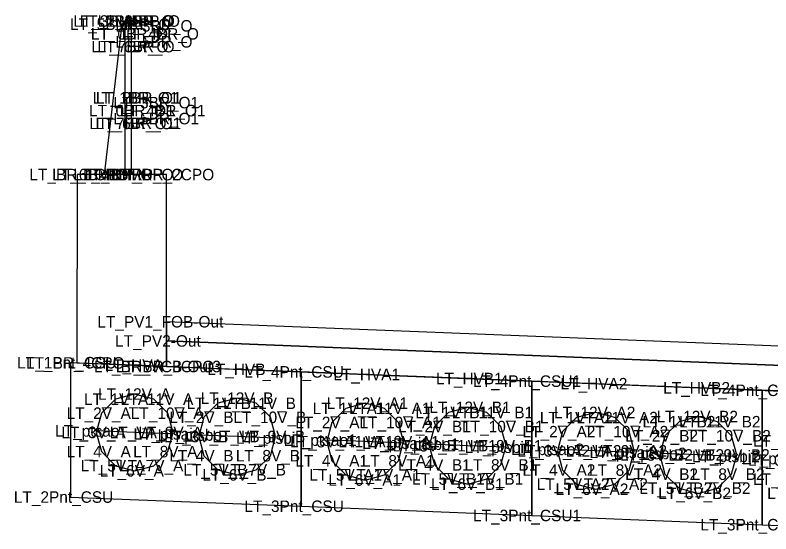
# Model space of a CAD drawing. Extents: x -26 to 1163, y -10 to 9537.
# Drawn here: x 59.53 to 69.36, y 6515.57 to 6522.32 of the extents above; entities that cross this region are included whole.
import ezdxf

# ---------------------------------------------------------------- set-up
doc = ezdxf.new("R2010")
doc.units = 0
for name, color, linetype in [('Prop CMT Bridge Metal Rail', 7, 'Continuous'), ('Prop CMT Bridge Metal Rail Post', 7, 'Continuous'), ('Prop CMT Concrete Structures', 7, 'Continuous'), ('Prop CMT Corridor Surface Symbology Blue', 7, 'Continuous'), ('Prop CMT Pvmt Course 1', 7, 'Continuous'), ('Prop CMT Pvmt Course 2', 7, 'Continuous'), ('Scratch_Level_0', 7, 'Continuous')]:
    doc.layers.add(name, color=color, linetype=linetype)

msp = doc.modelspace()

# ---------------------------------------------------------------- linework, layer by layer
at = {"layer": 'Prop CMT Bridge Metal Rail'}
for points in [[(61.0407, 6522.2467), (61.124, 6522.2467), (61.3532, 6522.1842), (61.4365, 6522.08)], [(61.0407, 6522.08), (61.0407, 6522.2467)], [(61.4365, 6522.08), (61.3532, 6521.9759), (61.124, 6521.9134), (61.0407, 6521.9134)], [(61.0407, 6521.9134), (61.0407, 6522.08)], [(61.0407, 6521.2467), (61.124, 6521.2467), (61.3532, 6521.1842), (61.4365, 6521.08)], [(61.0407, 6521.08), (61.0407, 6521.2467)], [(61.4365, 6521.08), (61.3532, 6520.9759), (61.124, 6520.9134), (61.0407, 6520.9134)], [(61.0407, 6520.9134), (61.0407, 6521.08)]]:
    msp.add_lwpolyline(points, dxfattribs=at)
at = {"layer": 'Prop CMT Bridge Metal Rail Post'}
for points in [[(60.9574, 6522.2467), (60.9157, 6522.205), (60.6865, 6520.2467)], [(61.0407, 6522.2467), (60.9574, 6522.2467)], [(60.9574, 6522.2467), (60.9574, 6520.2467)], [(61.0407, 6520.2467), (61.0407, 6522.2467)]]:
    msp.add_lwpolyline(points, dxfattribs=at)
at = {"layer": 'Prop CMT Concrete Structures'}
for points in [[(61.5, 6517.7467), (61.499, 6520.2467), (60.3343, 6520.2467), (60.3333, 6517.7934)], [(63.25, 6517.6767), (62.4167, 6517.71), (61.0833, 6517.7634), (60.25, 6517.7967)], [(60.25, 6517.7967), (60.25, 6516.0467)], [(60.3333, 6517.7934), (61.5, 6517.7467)], [(66.25, 6517.5567), (65.4167, 6517.59), (64.0833, 6517.6434), (63.25, 6517.6767)], [(63.25, 6517.6767), (63.25, 6515.9267)], [(63.25, 6515.9267), (63.25, 6517.6767)], [(69.25, 6517.4367), (68.4167, 6517.47), (67.0833, 6517.5234), (66.25, 6517.5567)], [(66.25, 6517.5567), (66.25, 6515.8067)], [(66.25, 6515.8067), (66.25, 6517.5567)], [(61.0833, 6517.3884), (60.8333, 6517.3214), (60.6503, 6517.1384), (60.5833, 6516.8884)], [(61.5833, 6516.8884), (61.5163, 6517.1384), (61.3333, 6517.3214), (61.0833, 6517.3884)], [(72.25, 6517.3167), (71.4167, 6517.35), (70.0833, 6517.4034), (69.25, 6517.4367)], [(69.25, 6517.4367), (69.25, 6515.6867)], [(69.25, 6515.6867), (69.25, 6517.4367)], [(62.4167, 6517.335), (62.1667, 6517.268), (61.9837, 6517.085), (61.9167, 6516.835)], [(62.9167, 6516.835), (62.8497, 6517.085), (62.6667, 6517.268), (62.4167, 6517.335)], [(64.0833, 6517.2684), (63.8333, 6517.2014), (63.6503, 6517.0184), (63.5833, 6516.7684)], [(64.5833, 6516.7684), (64.5163, 6517.0184), (64.3333, 6517.2014), (64.0833, 6517.2684)], [(65.4167, 6517.215), (65.1667, 6517.148), (64.9837, 6516.965), (64.9167, 6516.715)], [(65.9167, 6516.715), (65.8497, 6516.965), (65.6667, 6517.148), (65.4167, 6517.215)], [(67.0833, 6517.1484), (66.8333, 6517.0814), (66.6503, 6516.8984), (66.5833, 6516.6484)], [(67.5833, 6516.6484), (67.5163, 6516.8984), (67.3333, 6517.0814), (67.0833, 6517.1484)], [(68.4167, 6517.095), (68.1667, 6517.028), (67.9837, 6516.845), (67.9167, 6516.595)], [(68.9167, 6516.595), (68.8497, 6516.845), (68.6667, 6517.028), (68.4167, 6517.095)], [(60.5833, 6516.8884), (60.6503, 6516.6384), (60.8333, 6516.4554), (61.0833, 6516.3884), (61.3333, 6516.4554), (61.5163, 6516.6384), (61.5833, 6516.8884)], [(61.9167, 6516.835), (61.9837, 6516.585), (62.1667, 6516.402), (62.4167, 6516.335), (62.6667, 6516.402), (62.8497, 6516.585), (62.9167, 6516.835)], [(63.5833, 6516.7684), (63.6503, 6516.5184), (63.8333, 6516.3354), (64.0833, 6516.2684), (64.3333, 6516.3354), (64.5163, 6516.5184), (64.5833, 6516.7684)], [(64.9167, 6516.715), (64.9837, 6516.465), (65.1667, 6516.282), (65.4167, 6516.215), (65.6667, 6516.282), (65.8497, 6516.465), (65.9167, 6516.715)], [(66.5833, 6516.6484), (66.6503, 6516.3984), (66.8333, 6516.2154), (67.0833, 6516.1484), (67.3333, 6516.2154), (67.5163, 6516.3984), (67.5833, 6516.6484)], [(67.9167, 6516.595), (67.9837, 6516.345), (68.1667, 6516.162), (68.4167, 6516.095), (68.6667, 6516.162), (68.8497, 6516.345), (68.9167, 6516.595)], [(60.25, 6516.0467), (63.25, 6515.9267)], [(63.25, 6515.9267), (66.25, 6515.8067)], [(66.25, 6515.8067), (69.25, 6515.6867)], [(69.25, 6515.6867), (72.25, 6515.5667)]]:
    msp.add_lwpolyline(points, dxfattribs=at)
at = {"layer": 'Prop CMT Corridor Surface Symbology Blue'}
for points in [[(61.5733, 6516.8688), (61.0833, 6516.8884), (60.5933, 6516.908)], [(62.9067, 6516.8154), (62.4167, 6516.835), (61.9267, 6516.8546)], [(64.5733, 6516.7488), (64.0833, 6516.7684), (63.5933, 6516.788)], [(65.9067, 6516.6954), (65.4167, 6516.715), (64.9267, 6516.7346)], [(67.5733, 6516.6288), (67.0833, 6516.6484), (66.5933, 6516.668)], [(68.9067, 6516.5754), (68.4167, 6516.595), (67.9267, 6516.6146)]]:
    msp.add_lwpolyline(points, dxfattribs=at)
at = {"layer": 'Prop CMT Pvmt Course 1'}
for points in [[(80, 6517.59), (71, 6517.95), (61.4998, 6518.33)], [(61.4998, 6518.33), (61.4999, 6518.08)], [(61.4999, 6518.08), (80, 6517.34)]]:
    msp.add_lwpolyline(points, dxfattribs=at)
at = {"layer": 'Prop CMT Pvmt Course 2'}
for points in [[(80, 6517.34), (61.4999, 6518.08)], [(61.4999, 6518.08), (61.5, 6517.7467), (80, 6517.0067)]]:
    msp.add_lwpolyline(points, dxfattribs=at)

# ---------------------------------------------------------------- texts
at = {"layer": 'Scratch_Level_0'}
for s, p in [('LT_3BMRP_O', (60.2853, 6522.1717)), ('LT_2BMRP_O', (60.3687, 6522.1717)), ('LT_2BR_O', (60.6032, 6522.1717)), ('LT_5BMRP_O', (60.2437, 6522.13)), ('LT_3BR_O', (60.8323, 6522.1092)), ('LT_0BR_O', (60.5139, 6522.005)), ('LT_4BR_O', (60.9157, 6522.005)), ('LT_5BR_O', (60.8323, 6521.9009)), ('LT_7BR_O', (60.5198, 6521.8384)), ('LT_6BR_O', (60.5996, 6521.8384)), ('LT_1BR_O1', (60.5376, 6521.1717)), ('LT_2BR_O1', (60.5784, 6521.1717)), ('LT_3BR_O1', (60.8075, 6521.1092)), ('LT_0BR_O1', (60.4891, 6521.005)), ('LT_4BR_O1', (60.8909, 6521.005)), ('LT_5BR_O1', (60.8075, 6520.9009)), ('LT_7BR_O1', (60.495, 6520.8384)), ('LT_6BR_O1', (60.5748, 6520.8384)), ('LT_BR_1CPO', (59.7143, 6520.1717)), ('LT_6BMRP_O', (60.0109, 6520.1717)), ('LT_4BMRP_O', (60.2853, 6520.1717)), ('LT_1BMRP_O', (60.4112, 6520.1717)), ('LT_BR_2CPO', (60.8364, 6520.1717)), ('LT_PV1_FOB-Out', (60.5986, 6518.255)), ('LT_PV2-Out', (60.829, 6518.005)), ('LT_1Pnt_CSU', (59.5543, 6517.7217)), ('LT_BR_4CPO', (59.6707, 6517.7184)), ('LT_BR_VCB-Out3', (60.5552, 6517.6717)), ('LT_HVA', (60.6924, 6517.6884)), ('LT_BR_3CPO', (60.8374, 6517.6717)), ('LT_HVB', (62.0281, 6517.635)), ('LT_4Pnt_CSU', (62.5118, 6517.6017)), ('LT_HVA1', (63.6676, 6517.5684)), ('LT_HVB1', (65.0033, 6517.515)), ('LT_4Pnt_CSU1', (65.487, 6517.4817)), ('LT_HVA2', (66.6251, 6517.4484)), ('LT_HVB2', (67.9608, 6517.395)), ('LT_4Pnt_CSU2', (68.4445, 6517.3617)), ('LT_1V_A', (60.4235, 6517.2464)), ('LT_12V_A', (60.6062, 6517.3134)), ('LT_11V_A', (60.8987, 6517.2464)), ('LT_12V_B', (61.9419, 6517.26)), ('LT_1V_B', (61.7592, 6517.193)), ('LT_11V_B', (62.2344, 6517.193)), ('LT_12V_A1', (63.5814, 6517.1934)), ('LT_12V_B1', (64.9171, 6517.14)), ('LT_2V_A', (60.198, 6517.0634)), ('LT_10V_A', (61.0333, 6517.0634)), ('LT_1V_A1', (63.3987, 6517.1264)), ('LT_11V_A1', (63.8739, 6517.1264)), ('LT_1V_B1', (64.7344, 6517.073)), ('LT_11V_B1', (65.2096, 6517.073)), ('LT_12V_A2', (66.5388, 6517.0734)), ('LT_2V_B', (61.5337, 6517.01)), ('LT_10V_B', (62.369, 6517.01)), ('LT_2V_A1', (63.1732, 6516.9434)), ('LT_10V_A1', (64.0085, 6516.9434)), ('LT_1V_A2', (66.3562, 6517.0064)), ('LT_11V_A2', (66.8314, 6517.0064)), ('LT_1V_B2', (67.6919, 6516.953)), ('LT_12V_B2', (67.8745, 6517.02)), ('LT_11V_B2', (68.1671, 6516.953)), ('LT_2V_B1', (64.5089, 6516.89)), ('LT_10V_B1', (65.3442, 6516.89)), ('LT_ptsao', (60.0488, 6516.833)), ('LT_3V_A', (60.131, 6516.8134)), ('LT_VA', (60.7597, 6516.8134)), ('LT_ptsai', (61.069, 6516.7938)), ('LT_9V_A', (61.131, 6516.8134)), ('LT_ptsbo', (61.3834, 6516.7796)), ('LT_3V_B', (61.4667, 6516.76)), ('LT_VB', (62.0954, 6516.76)), ('LT_ptsbi', (62.4035, 6516.7404)), ('LT_9V_B', (62.4667, 6516.76)), ('LT_2V_A2', (66.1306, 6516.8234)), ('LT_10V_A2', (66.966, 6516.8234)), ('LT_2V_B2', (67.4663, 6516.77)), ('LT_10V_B2', (68.3016, 6516.77)), ('LT_ptsao1', (63.024, 6516.713)), ('LT_3V_A1', (63.1062, 6516.6934)), ('LT_VA1', (63.7349, 6516.6934)), ('LT_ptsai1', (64.0442, 6516.6738)), ('LT_9V_A1', (64.1062, 6516.6934)), ('LT_ptsbo1', (64.3586, 6516.6596)), ('LT_3V_B1', (64.4419, 6516.64)), ('LT_VB1', (65.0706, 6516.64)), ('LT_9V_B1', (65.4419, 6516.64)), ('LT_2V_A3', (69.1306, 6516.7034)), ('LT_4V_A', (60.198, 6516.5634)), ('LT_8V_A', (61.064, 6516.5634)), ('LT_ptsbi1', (65.3787, 6516.6204)), ('LT_ptsao2', (65.9815, 6516.593)), ('LT_3V_A2', (66.0636, 6516.5734)), ('LT_VA2', (66.6924, 6516.5734)), ('LT_ptsai2', (67.0017, 6516.5538)), ('LT_9V_A2', (67.0636, 6516.5734)), ('LT_ptsbo2', (67.316, 6516.5396)), ('LT_4V_B', (61.5337, 6516.51)), ('LT_8V_B', (62.3997, 6516.51)), ('LT_4V_A1', (63.1732, 6516.4434)), ('LT_8V_A1', (64.0392, 6516.4434)), ('LT_3V_B2', (67.3993, 6516.52)), ('LT_VB2', (68.0281, 6516.52)), ('LT_ptsbi2', (68.3362, 6516.5004)), ('LT_9V_B2', (68.3993, 6516.52)), ('LT_ptsao3', (68.9815, 6516.473)), ('LT_3V_A3', (69.0636, 6516.4534)), ('LT_5V_A', (60.381, 6516.3804)), ('LT_7V_A', (60.881, 6516.3804)), ('LT_4V_B1', (64.5089, 6516.39)), ('LT_8V_B1', (65.3749, 6516.39)), ('LT_6V_A', (60.6274, 6516.3134)), ('LT_5V_B', (61.7167, 6516.327)), ('LT_6V_B', (61.9631, 6516.26)), ('LT_7V_B', (62.2167, 6516.327)), ('LT_5V_A1', (63.3562, 6516.2604)), ('LT_7V_A1', (63.8562, 6516.2604)), ('LT_4V_A2', (66.1306, 6516.3234)), ('LT_8V_A2', (66.9967, 6516.3234)), ('LT_4V_B2', (67.4663, 6516.27)), ('LT_8V_B2', (68.3324, 6516.27)), ('LT_6V_A1', (63.6026, 6516.1934)), ('LT_5V_B1', (64.6919, 6516.207)), ('LT_7V_B1', (65.1919, 6516.207)), ('LT_4V_A3', (69.1306, 6516.2034)), ('LT_6V_B1', (64.9383, 6516.14)), ('LT_5V_A2', (66.3136, 6516.1404)), ('LT_6V_A2', (66.5601, 6516.0734)), ('LT_7V_A2', (66.8136, 6516.1404)), ('LT_5V_B2', (67.6493, 6516.087)), ('LT_7V_B2', (68.1493, 6516.087)), ('LT_2Pnt_CSU', (59.5118, 6515.9717)), ('LT_6V_B2', (67.8958, 6516.02)), ('LT_5V_A3', (69.3136, 6516.0204)), ('LT_3Pnt_CSU', (62.5118, 6515.8517)), ('LT_3Pnt_CSU1', (65.487, 6515.7317)), ('LT_3Pnt_CSU2', (68.4445, 6515.6117))]:
    msp.add_text(s, height=0.15, dxfattribs=at).set_placement(p)

doc.saveas('drawing.dxf')
